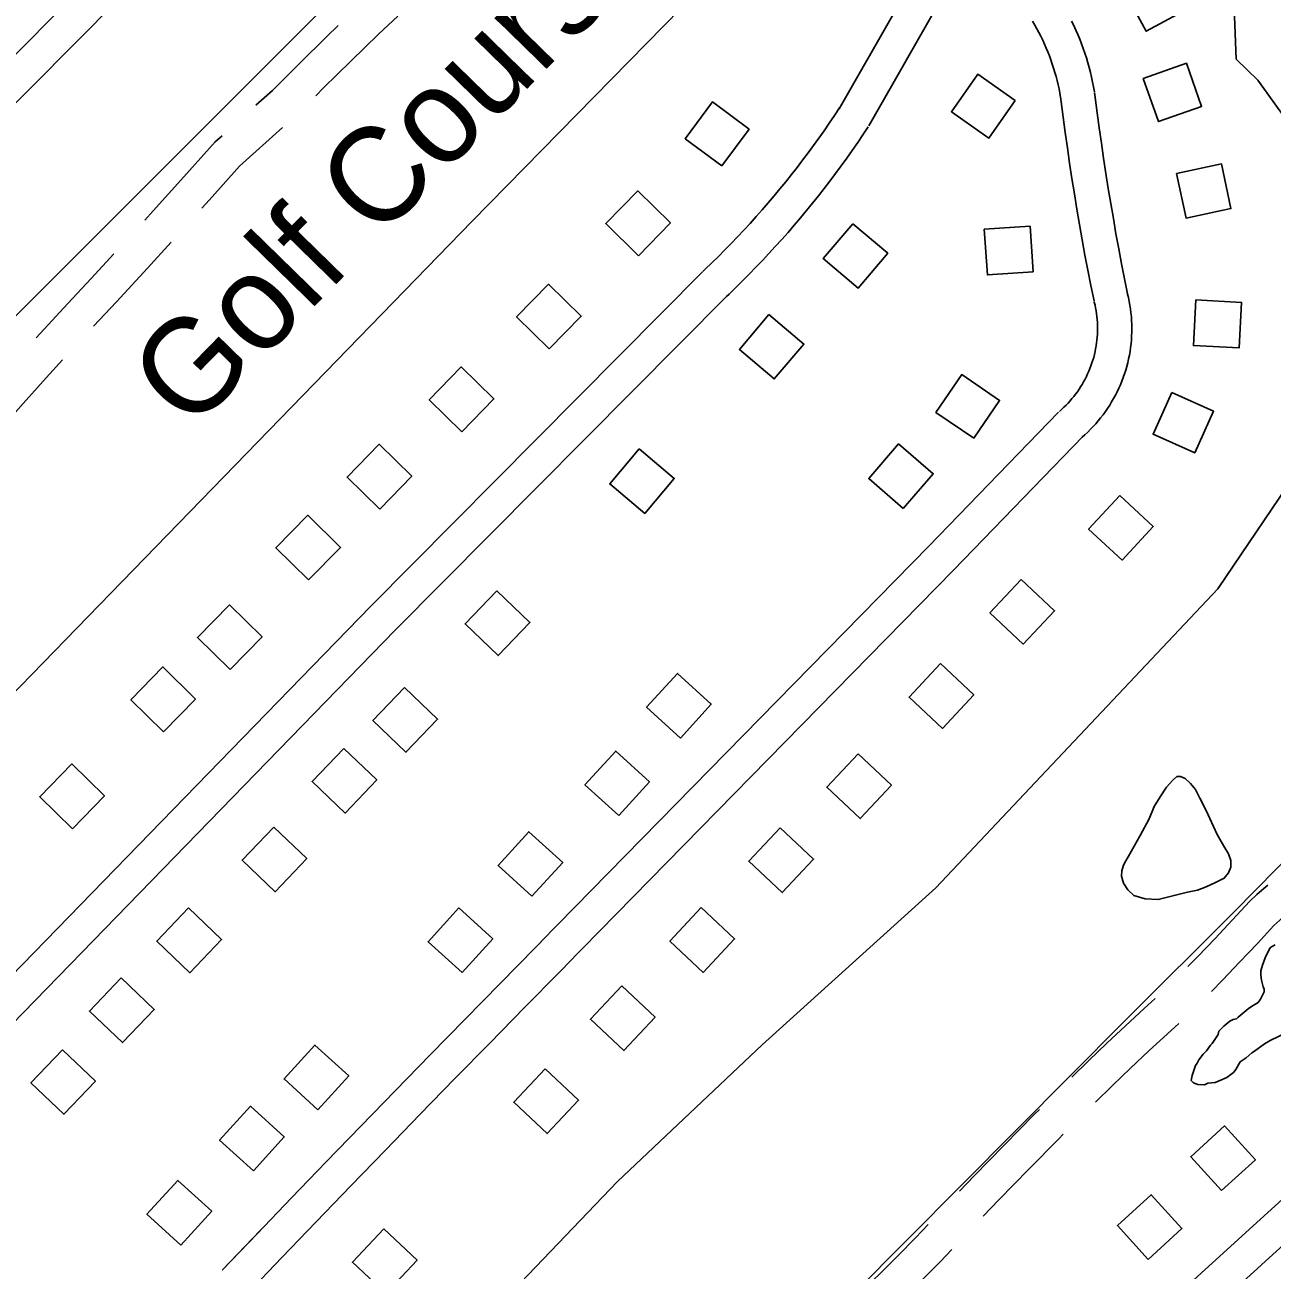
# Model space of a CAD drawing. Extents: x 3568792 to 3606828, y 529143 to 554785.
# Drawn here: x 3585665 to 3586755, y 539354 to 540442 of the extents above; entities that cross this region are included whole.
import ezdxf

# ---------------------------------------------------------------- set-up
doc = ezdxf.new("R2010")
doc.units = 0
for name, color, linetype in [('V-BLDG-IDEN', 7, 'Continuous'), ('V-BLDG-OTLN', 7, 'Continuous'), ('V-ROAD-CNTR', 7, 'Continuous'), ('V-SITE-OTLN', 7, 'Continuous'), ('V-SITE-VEGE', 7, 'Continuous'), ('V-TOPO-SHOR', 7, 'Continuous')]:
    doc.layers.add(name, color=color, linetype=linetype)

msp = doc.modelspace()

# ---------------------------------------------------------------- linework, layer by layer
at = {"layer": 'V-BLDG-OTLN'}
for points in [[(3586626, 540471.9), (3586645.1, 540436.8), (3586680.2, 540455.8), (3586661.2, 540491)], [(3586642.6, 540395.6), (3586655.8, 540357.9), (3586693.6, 540371.1), (3586680.3, 540408.9)], [(3586530.6, 540376.3), (3586497.9, 540399.2), (3586474.9, 540366.5), (3586507.6, 540343.5)], [(3586274.2, 540319.1), (3586298, 540351.2), (3586265.9, 540375), (3586242.1, 540342.9)], [(3586671.7, 540312.6), (3586680, 540273.5), (3586719.1, 540281.8), (3586710.8, 540320.9)], [(3586201.2, 540240.6), (3586229.2, 540269.2), (3586200.6, 540297.2), (3586172.6, 540268.6)], [(3586388.6, 540268.5), (3586362.8, 540238), (3586393.3, 540212.2), (3586419.2, 540242.7)], [(3586546.2, 540226.4), (3586543.6, 540266.3), (3586503.6, 540263.7), (3586506.3, 540223.8)], [(3586123.3, 540159.1), (3586151.3, 540187.7), (3586122.7, 540215.7), (3586094.7, 540187.1)], [(3586688.5, 540201.9), (3586686.4, 540162), (3586726.3, 540159.9), (3586728.5, 540199.8)], [(3586315.3, 540189.1), (3586289.5, 540158.6), (3586320, 540132.8), (3586345.9, 540163.3)], [(3586046.9, 540086.7), (3586074.9, 540115.3), (3586046.3, 540143.3), (3586018.3, 540114.7)], [(3586494.4, 540081.1), (3586516.9, 540114.1), (3586483.8, 540136.7), (3586461.3, 540103.6)], [(3586667.5, 540121), (3586651.1, 540084.6), (3586687.6, 540068.1), (3586704, 540104.6)], [(3585975.1, 540019.1), (3586003.1, 540047.7), (3585974.5, 540075.7), (3585946.5, 540047.1)], [(3586202, 540071.6), (3586176.2, 540041), (3586206.8, 540015.2), (3586232.6, 540045.8)], [(3586432.8, 540019.6), (3586458.9, 540049.9), (3586428.7, 540076), (3586402.5, 540045.7)], [(3586622, 540030.9), (3586594.8, 540001.6), (3586624.1, 539974.4), (3586651.3, 540003.7)], [(3585912.9, 539957.1), (3585940.9, 539985.6), (3585912.3, 540013.6), (3585884.3, 539985.1)], [(3586535.9, 539957.5), (3586508.5, 539928.4), (3586537.6, 539901), (3586565, 539930.2)], [(3586077.4, 539947.5), (3586049.7, 539918.6), (3586078.6, 539890.9), (3586106.3, 539919.8)], [(3585844.3, 539878.8), (3585872.3, 539907.3), (3585843.7, 539935.3), (3585815.7, 539906.8)], [(3586465.2, 539883.9), (3586437.8, 539854.7), (3586467, 539827.3), (3586494.3, 539856.5)], [(3585786, 539824.4), (3585814, 539853), (3585785.5, 539881), (3585757.5, 539852.4)], [(3586238, 539818.9), (3586264.9, 539848.5), (3586235.3, 539875.4), (3586208.4, 539845.8)], [(3585996.7, 539863), (3585969.1, 539834.1), (3585998, 539806.4), (3586025.6, 539835.3)], [(3585943.6, 539809.8), (3585915.9, 539780.9), (3585944.8, 539753.3), (3585972.5, 539782.2)], [(3586184, 539751), (3586210.9, 539780.6), (3586181.4, 539807.5), (3586154.4, 539778)], [(3586393.3, 539805), (3586365.9, 539775.9), (3586395.1, 539748.5), (3586422.4, 539777.6)], [(3585706.4, 539739.6), (3585734.4, 539768.2), (3585705.8, 539796.2), (3585677.8, 539767.6)], [(3585882.4, 539741), (3585854.7, 539712.1), (3585883.7, 539684.5), (3585911.3, 539713.4)], [(3586108, 539680.5), (3586135, 539710.1), (3586105.4, 539737), (3586078.5, 539707.4)], [(3586325.1, 539740.4), (3586297.7, 539711.2), (3586326.9, 539683.8), (3586354.3, 539713)], [(3585807.8, 539670.3), (3585780.2, 539641.4), (3585809.1, 539613.7), (3585836.8, 539642.7)], [(3586047, 539613.8), (3586073.9, 539643.4), (3586044.3, 539670.3), (3586017.4, 539640.7)], [(3586256.2, 539670.6), (3586228.8, 539641.4), (3586257.9, 539614), (3586285.3, 539643.2)], [(3585749, 539609.1), (3585721.3, 539580.2), (3585750.2, 539552.6), (3585777.9, 539581.5)], [(3586186.7, 539602.1), (3586159.3, 539573), (3586188.5, 539545.6), (3586215.8, 539574.7)], [(3585697.7, 539546.4), (3585670.1, 539517.5), (3585699, 539489.9), (3585726.6, 539518.8)], [(3585921.1, 539493.9), (3585948, 539523.4), (3585918.4, 539550.4), (3585891.5, 539520.8)], [(3586119.7, 539529.6), (3586092.3, 539500.4), (3586121.5, 539473), (3586148.9, 539502.2)], [(3585864.7, 539440.5), (3585891.6, 539470.1), (3585862, 539497), (3585835.1, 539467.4)], [(3586711, 539423.2), (3586740.6, 539450.1), (3586713.6, 539479.7), (3586684, 539452.8)], [(3585801.2, 539375.6), (3585828.2, 539405.2), (3585798.6, 539432.1), (3585771.6, 539402.5)], [(3586646.8, 539363), (3586676.4, 539389.9), (3586649.5, 539419.5), (3586619.9, 539392.6)], [(3585978.6, 539389.8), (3585951.2, 539360.6), (3585980.3, 539333.2), (3586007.7, 539362.4)]]:
    msp.add_lwpolyline(points, close=True, dxfattribs=at)
at = {"layer": 'V-ROAD-CNTR'}
msp.add_line((3586487.9, 540503.4), (3586402.6, 540354.1), dxfattribs=at)
for points in [[(3586462.1, 541227.8), (3586217.7, 540981.6), (3585917.8, 540679.7), (3585610.2, 540370.1), (3585316.2, 540077), (3584972.9, 539741.6), (3584657.8, 539429.3), (3584319.3, 539087.8), (3584189.3, 538953.7), (3583891.2, 538658.6)], [(3586481.7, 541205), (3586238.9, 540960.4), (3585939.1, 540658.6), (3585631.5, 540348.9), (3585337.3, 540055.7), (3584994, 539720.2), (3584679, 539408.1), (3584340.7, 539066.8), (3584227.9, 538939.5)], [(3586601.6, 540761.2), (3586469.4, 540531.4), (3586376.6, 540369)], [(3585938.7, 540441.8), (3585928.9, 540432.3), (3585904.8, 540408.6), (3585881.2, 540385), (3585866.9, 540372.2)], [(3585990.8, 540450.1), (3585974, 540434.2), (3585949.9, 540410.8), (3585925.9, 540387.3), (3585919.1, 540380.4)], [(3586570.3, 540378.8), (3586569.6, 540382.7), (3586568.9, 540386.4), (3586568.1, 540390), (3586567.2, 540393.7), (3586566.3, 540397.3), (3586565.3, 540400.9), (3586564.2, 540404.5), (3586563, 540408.1), (3586561.8, 540411.7), (3586560.5, 540415.2), (3586559.2, 540418.7), (3586557.7, 540422.1), (3586556.2, 540425.6), (3586554.7, 540429), (3586553, 540432.4), (3586551.3, 540435.7), (3586549.6, 540439), (3586547.7, 540442.3), (3586545.8, 540445.6)], [(3586599.8, 540384), (3586599.1, 540388.2), (3586598.3, 540392.4), (3586597.3, 540396.7), (3586596.3, 540400.9), (3586595.2, 540405.1), (3586594.1, 540409.3), (3586592.8, 540413.5), (3586591.5, 540417.6), (3586590.1, 540421.7), (3586588.6, 540425.8), (3586587, 540429.8), (3586585.3, 540433.9), (3586583.6, 540437.8), (3586581.8, 540441.8), (3586579.9, 540445.7)], [(3586599.5, 540201.2), (3586596.8, 540214.5), (3586594.2, 540227.8), (3586591.6, 540241.1), (3586589.2, 540254.5), (3586586.8, 540267.8), (3586584.5, 540281.2), (3586582.3, 540294.6), (3586580.2, 540308), (3586578.1, 540321.4), (3586576.2, 540334.8), (3586574.3, 540348.3), (3586572.4, 540361.7), (3586570.7, 540375.2), (3586570.2, 540379.6)], [(3586628.9, 540207.2), (3586626.2, 540220.3), (3586623.6, 540233.5), (3586621.1, 540246.6), (3586618.7, 540259.8), (3586616.4, 540273), (3586614.1, 540286.2), (3586611.9, 540299.4), (3586609.8, 540312.6), (3586607.8, 540325.9), (3586605.9, 540339.1), (3586604, 540352.4), (3586602.2, 540365.6), (3586600.5, 540378.9), (3586599.9, 540383.3)], [(3586377.1, 540369.8), (3586372.6, 540363.1), (3586368.1, 540356.5), (3586363.6, 540349.9), (3586359, 540343.4), (3586354.3, 540336.9), (3586349.6, 540330.5), (3586344.8, 540324.1), (3586339.9, 540317.8), (3586335, 540311.5), (3586330, 540305.2), (3586324.9, 540299), (3586319.8, 540292.9), (3586314.6, 540286.8), (3586309.4, 540280.8), (3586304.1, 540274.8), (3586298.8, 540268.8), (3586293.4, 540262.9), (3586287.9, 540257.1), (3586282.4, 540251.3), (3586276.8, 540245.6), (3586271.2, 540240), (3586265.5, 540234.3), (3586259.7, 540228.8), (3586257.6, 540226.7)], [(3585890.2, 540352.8), (3585852.4, 540318.9), (3585826.3, 540289.5), (3585819.6, 540282.1)], [(3586402.1, 540353.2), (3586397.5, 540346.4), (3586392.9, 540339.5), (3586388.2, 540332.7), (3586383.4, 540325.9), (3586378.5, 540319.2), (3586373.6, 540312.6), (3586368.6, 540305.9), (3586363.6, 540299.4), (3586358.5, 540292.8), (3586353.3, 540286.4), (3586348.1, 540280), (3586342.8, 540273.6), (3586337.4, 540267.3), (3586332, 540261), (3586326.5, 540254.8), (3586320.9, 540248.6), (3586315.3, 540242.5), (3586309.7, 540236.5), (3586303.9, 540230.5), (3586298.2, 540224.6), (3586292.3, 540218.7), (3586286.4, 540212.9), (3586280.5, 540207.1), (3586278.3, 540205)], [(3585837.2, 540345.5), (3585831.1, 540340.1), (3585803.9, 540309.5), (3585777.1, 540279.7), (3585769.7, 540271.7)], [(3585792.8, 540252.5), (3585772.2, 540229.8), (3585744.9, 540200.3), (3585724.9, 540179)], [(3585742.7, 540242.2), (3585722.9, 540220.7), (3585702.3, 540198.7), (3585681.7, 540176.4), (3585674.8, 540168.8)], [(3586257.3, 540226.4), (3585967.3, 539934.3), (3585581.1, 539537.1), (3585206.9, 539157.7), (3584878.7, 538819), (3584780.9, 538716.7)], [(3586278.6, 540205.3), (3585988.7, 539913.3), (3585602.5, 539516.1), (3585228.4, 539136.7), (3584900.3, 538798.2), (3584770.9, 538662.9)], [(3586569.3, 540104.5), (3586571.3, 540106.3), (3586573.2, 540108.1), (3586575.1, 540109.9), (3586576.8, 540111.7), (3586578.6, 540113.6), (3586580.2, 540115.6), (3586581.9, 540117.6), (3586583.4, 540119.6), (3586585, 540121.7), (3586586.4, 540123.8), (3586587.8, 540125.9), (3586589.2, 540128.1), (3586590.4, 540130.4), (3586591.7, 540132.6), (3586592.8, 540134.9), (3586593.9, 540137.2), (3586595, 540139.6), (3586595.9, 540141.9), (3586596.8, 540144.3), (3586597.7, 540146.8), (3586598.5, 540149.2), (3586599.2, 540151.7), (3586599.8, 540154.2), (3586600.4, 540156.7), (3586600.9, 540159.2), (3586601.4, 540161.7), (3586601.7, 540164.3), (3586602, 540166.8), (3586602.3, 540169.4), (3586602.5, 540171.9), (3586602.6, 540174.5), (3586602.6, 540177.1), (3586602.5, 540179.6), (3586602.4, 540182.2), (3586602.3, 540184.8), (3586602, 540187.3), (3586601.7, 540189.9), (3586601.3, 540192.4), (3586600.9, 540194.9), (3586600.4, 540197.4), (3586599.7, 540200), (3586599.6, 540200.5)], [(3586589.1, 540082), (3586591.5, 540084.1), (3586594, 540086.4), (3586596.4, 540088.8), (3586598.7, 540091.2), (3586601, 540093.7), (3586603.2, 540096.3), (3586605.3, 540098.9), (3586607.4, 540101.6), (3586609.4, 540104.3), (3586611.3, 540107.1), (3586613.2, 540109.9), (3586614.9, 540112.8), (3586616.6, 540115.7), (3586618.2, 540118.7), (3586619.8, 540121.7), (3586621.2, 540124.7), (3586622.6, 540127.8), (3586623.8, 540130.9), (3586625, 540134.1), (3586626.2, 540137.3), (3586627.2, 540140.5), (3586628.1, 540143.7), (3586629, 540147), (3586629.7, 540150.3), (3586630.4, 540153.6), (3586631, 540156.9), (3586631.5, 540160.3), (3586631.9, 540163.6), (3586632.2, 540167), (3586632.4, 540170.4), (3586632.5, 540173.7), (3586632.6, 540177.1), (3586632.5, 540180.5), (3586632.4, 540183.8), (3586632.2, 540187.2), (3586631.8, 540190.6), (3586631.4, 540193.9), (3586630.9, 540197.3), (3586630.3, 540200.6), (3586629.7, 540203.9), (3586628.9, 540207.1), (3586628.7, 540207.8)], [(3585697.8, 540149.6), (3585683.6, 540133.9), (3585663.5, 540111.5), (3585643.5, 540088.8), (3585635.5, 540080.3), (3585630.9, 540075.3)], [(3586116, 539640.6), (3586455.2, 539986.6), (3586568.4, 540103.7)], [(3586137.4, 539619.6), (3586476.6, 539965.7), (3586590, 540082.8)], [(3586681.4, 539619), (3586690.2, 539628), (3586705.3, 539643.7), (3586720.3, 539659.7), (3586735.6, 539676.3), (3586741.9, 539682.1), (3586748, 539687.4), (3586751.5, 539690.3)], [(3586702.1, 539597.2), (3586711.7, 539607.1), (3586727.1, 539623.1), (3586742.3, 539639.2), (3586756.8, 539655.1), (3586761.9, 539659.7), (3586767.4, 539664.5), (3586772.2, 539668.4)], [(3585870.6, 539388.3), (3585837.7, 539353.8), (3585867.8, 539385.3), (3585898, 539416.8), (3585928.3, 539448.2), (3585958.5, 539479.5), (3585988.9, 539510.8), (3586019.3, 539542), (3586049.8, 539573.2), (3586080.3, 539604.3), (3586110.9, 539635.4), (3586116.1, 539640.6)], [(3585829.4, 539301.6), (3585859.4, 539333.1), (3585889.5, 539364.6), (3585919.6, 539396), (3585949.8, 539427.3), (3585980.1, 539458.6), (3586010.4, 539489.9), (3586040.8, 539521.1), (3586071.2, 539552.2), (3586101.7, 539583.3), (3586132.2, 539614.3), (3586137.4, 539619.5)], [(3586580.2, 539522.4), (3586594.7, 539536.6), (3586610.8, 539552), (3586627.1, 539567.2), (3586643.4, 539582.4), (3586653, 539591)], [(3586600.8, 539500.6), (3586615.6, 539515), (3586631.5, 539530.2), (3586647.5, 539545.3), (3586663.7, 539560.2), (3586673.6, 539569.2)], [(3586482, 539422.6), (3586494.8, 539436), (3586521, 539462.9), (3586547.3, 539489.6), (3586551.9, 539494.2)], [(3586502.7, 539400.8), (3586516.4, 539415.2), (3586542.4, 539441.9), (3586568.6, 539468.5), (3586572.5, 539472.4)], [(3586793.5, 539442.2), (3586289.1, 538983.2)], [(3586813.7, 539420), (3586309.3, 538961)], [(3586383.7, 539323), (3586397.8, 539336.4), (3586413.1, 539351.4), (3586428.4, 539366.5), (3586443.4, 539381.8), (3586454.5, 539393.6)], [(3586404.3, 539301.2), (3586418.6, 539314.8), (3586434.2, 539330), (3586449.6, 539345.4), (3586465, 539361), (3586475.1, 539371.7)]]:
    msp.add_lwpolyline(points, dxfattribs=at)
at = {"layer": 'V-SITE-OTLN'}
for points in [[(3585552.7, 540084), (3585991.9, 540523.2), (3586200.8, 540727), (3586478.8, 541001.3), (3586516.4, 540995), (3586525.7, 540985.4), (3586534.9, 540975.8), (3586545.6, 540939.8), (3586535.6, 540906.1), (3586511.6, 540830.9), (3586406.2, 540619.6), (3586365.9, 540577), (3586330.2, 540550.7), (3586055.8, 540270.7), (3585581.9, 539783)], [(3586098.3, 539342.7), (3586182.8, 539431.2), (3586309.4, 539550.7), (3586461.1, 539687.9), (3586707.6, 539949.2), (3586768.6, 540039.5), (3586787.4, 540084.8), (3586813.7, 540167.4), (3586820.5, 540241.9), (3586805, 540307.2), (3586742.8, 540394), (3586723.8, 540412.3), (3586717, 540585.3)], [(3586972.5, 540399.8), (3586980.8, 540315.3), (3586975.3, 540237.9), (3586962.3, 540120.6), (3586936.8, 540009), (3586897.6, 539894.8), (3586860.2, 539815.2), (3586796.8, 539743), (3586722.1, 539666.8), (3586626.5, 539571.6), (3586388.6, 539332.2)]]:
    msp.add_lwpolyline(points, dxfattribs=at)
at = {"layer": 'V-SITE-VEGE'}
msp.add_lwpolyline([(3586768, 539561.4), (3586753.5, 539554.3), (3586748.4, 539551.4), (3586739.7, 539545), (3586737.5, 539543.6), (3586732.4, 539539.3), (3586727.3, 539535.7), (3586723.6, 539529.2), (3586721.4, 539526.4), (3586715.6, 539522.1), (3586709, 539519.2), (3586705.4, 539517.8), (3586698.9, 539517.2), (3586696, 539515.7), (3586690.2, 539515.8), (3586686.6, 539517.3), (3586684.4, 539519.5), (3586685.2, 539523.8), (3586688.2, 539532.5), (3586689.6, 539534.6), (3586691.1, 539537.5), (3586694.8, 539542.5), (3586697.7, 539545.4), (3586701.4, 539550.4), (3586702.8, 539551.9), (3586708, 539559.8), (3586708.7, 539562.7), (3586713.1, 539567), (3586718.2, 539571.3), (3586721.1, 539572.7), (3586724, 539573.4), (3586725.5, 539574.8), (3586734.2, 539582), (3586737.1, 539584.1), (3586742.9, 539587.7), (3586745.1, 539590.6), (3586746.6, 539593.4), (3586748.1, 539597), (3586748.1, 539599.2), (3586747.4, 539601.4), (3586746, 539607.2), (3586745.3, 539611.5), (3586745.4, 539615.2), (3586746.9, 539620.2), (3586749.1, 539626.7), (3586752.8, 539634.6), (3586754.2, 539636.1), (3586757.9, 539638.2)], dxfattribs=at)
at = {"layer": 'V-TOPO-SHOR'}
msp.add_lwpolyline([(3586629.3, 539715.1), (3586639.7, 539733.6), (3586647.8, 539748.2), (3586652.2, 539759.1), (3586657.2, 539767.6), (3586662.8, 539775.9), (3586668.5, 539781.9), (3586672, 539785.3), (3586675.2, 539785.2), (3586679.1, 539783.5), (3586683.7, 539779.2), (3586688.2, 539774), (3586692, 539766.3), (3586697.5, 539755.4), (3586707.2, 539734.4), (3586712.9, 539724.2), (3586717, 539717.6), (3586719.1, 539711.9), (3586719, 539706), (3586717.2, 539700.9), (3586713.4, 539696.3), (3586705.8, 539692.5), (3586697.6, 539688.7), (3586690, 539685.9), (3586681.1, 539684.1), (3586669.5, 539681.3), (3586655.7, 539677.6), (3586644.2, 539678.3), (3586634.2, 539681.2), (3586629.1, 539686.2), (3586625.3, 539691.9), (3586623.4, 539698), (3586623.7, 539702.7), (3586625.3, 539707.6), (3586627.3, 539711.5), (3586629.3, 539715.1)], dxfattribs=at)

# ---------------------------------------------------------------- texts
at = {"layer": 'V-BLDG-IDEN'}
msp.add_text('Golf Course', height=83, rotation=45.6614, dxfattribs=at).set_placement((3585809.5, 540085.1))

doc.saveas('drawing.dxf')
